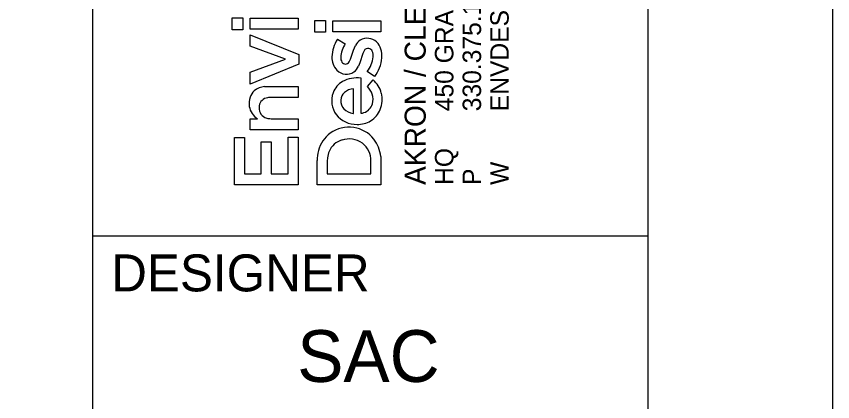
# Model space of a CAD drawing. Extents: x -1.3 to 34, y -0.5 to 22.
# Drawn here: x 31.794 to 34, y 2.552 to 3.594 of the extents above; entities that cross this region are included whole.
import ezdxf

# ---------------------------------------------------------------- set-up
doc = ezdxf.new("R2010")
doc.units = 0
for name, color, linetype in [('SH_Border', 7, 'Continuous'), ('SH_Cut_Line', 7, 'Continuous'), ('SH_Data', 7, 'Continuous')]:
    doc.layers.add(name, color=color, linetype=linetype)

msp = doc.modelspace()

# ---------------------------------------------------------------- linework, layer by layer
at = {"layer": 'SH_Border'}
for p, q in [((32, 0.5), (32, 21.5)), ((32, 3), (33.5, 3))]:
    msp.add_line(p, q, dxfattribs=at)
msp.add_lwpolyline([(1.5, 21.5), (33.5, 21.5), (33.5, 0.5), (1.5, 0.5)], close=True, dxfattribs=at)
at = {"layer": 'SH_Cut_Line'}
msp.add_lwpolyline([(0, 0), (34, 0), (34, 22), (0, 22)], close=True, dxfattribs=at)
at = {"layer": 'SH_Data'}
for p, q in [((32.3771, 3.5582), (32.3771, 3.5903)), ((32.3771, 3.5903), (32.4054, 3.5903)), ((32.4054, 3.5903), (32.4054, 3.5582)), ((32.4254, 3.5594), (32.4254, 3.5893)), ((32.4254, 3.5893), (32.5557, 3.5893)), ((32.5557, 3.5893), (32.5557, 3.5594)), ((32.6005, 3.5511), (32.6005, 3.5832)), ((32.6005, 3.5832), (32.6289, 3.5832)), ((32.6289, 3.5832), (32.6289, 3.5511)), ((32.6489, 3.5523), (32.6489, 3.5822)), ((32.6489, 3.5822), (32.7792, 3.5822)), ((32.7792, 3.5822), (32.7792, 3.5523)), ((32.4054, 3.5582), (32.3771, 3.5582)), ((32.5557, 3.5594), (32.4254, 3.5594)), ((32.7792, 3.5523), (32.6489, 3.5523)), ((32.4254, 3.5133), (32.4254, 3.5446)), ((32.4254, 3.5446), (32.5567, 3.4913)), ((32.6289, 3.5511), (32.6005, 3.5511)), ((32.6615, 3.5321), (32.6827, 3.5203)), ((32.5212, 3.478), (32.4254, 3.5133)), ((32.7048, 3.5026), (32.7104, 3.5153)), ((32.5567, 3.4913), (32.5567, 3.4644)), ((32.6967, 3.4787), (32.7048, 3.5026)), ((32.7298, 3.4933), (32.7221, 3.4688)), ((32.7334, 3.501), (32.7298, 3.4933)), ((32.4254, 3.4429), (32.5212, 3.478)), ((32.5567, 3.4644), (32.4254, 3.4109)), ((32.693, 3.4712), (32.6967, 3.4787)), ((32.7221, 3.4688), (32.7182, 3.4592)), ((32.4254, 3.4109), (32.4254, 3.4429)), ((32.7621, 3.4314), (32.742, 3.4447)), ((32.7245, 3.4275), (32.7246, 3.3319)), ((32.7423, 3.4046), (32.7577, 3.422)), ((32.4644, 3.404), (32.4729, 3.4044)), ((32.4729, 3.4044), (32.5557, 3.4044)), ((32.5557, 3.4044), (32.5557, 3.3746)), ((32.7049, 3.3318), (32.7049, 3.3983)), ((32.5557, 3.3746), (32.4814, 3.3746)), ((32.7036, 3.3317), (32.7049, 3.3318)), ((32.4254, 3.2875), (32.4254, 3.3173)), ((32.4254, 3.3173), (32.4455, 3.3173)), ((32.4822, 3.3173), (32.5557, 3.3173)), ((32.5557, 3.3173), (32.5557, 3.2876)), ((32.5557, 3.2876), (32.4254, 3.2875)), ((32.383, 3.1379), (32.383, 3.266)), ((32.383, 3.266), (32.4101, 3.266)), ((32.4101, 3.266), (32.4101, 3.1683)), ((32.5286, 3.1683), (32.5286, 3.2672)), ((32.5286, 3.2672), (32.5557, 3.2672)), ((32.5557, 3.2672), (32.5557, 3.1379)), ((32.455, 3.1683), (32.455, 3.2549)), ((32.455, 3.2549), (32.4822, 3.2549)), ((32.4822, 3.2549), (32.4822, 3.1683)), ((32.6064, 3.138), (32.6064, 3.204)), ((32.6347, 3.2118), (32.6341, 3.2023)), ((32.6341, 3.2023), (32.6341, 3.1684)), ((32.7515, 3.1683), (32.7515, 3.2024)), ((32.7785, 3.215), (32.7792, 3.2021)), ((32.7792, 3.2021), (32.7792, 3.138)), ((32.4101, 3.1683), (32.455, 3.1683)), ((32.4822, 3.1683), (32.5286, 3.1683)), ((32.6341, 3.1684), (32.7515, 3.1683)), ((32.5557, 3.1379), (32.383, 3.1379)), ((32.7792, 3.138), (32.6064, 3.138))]:
    msp.add_line(p, q, dxfattribs=at)
for points in [[(32.3771, 3.5582), (32.3771, 3.5903), (32.4054, 3.5903), (32.4054, 3.5582)], [(32.4254, 3.5594), (32.4254, 3.5893), (32.5557, 3.5893), (32.5557, 3.5594)], [(32.6005, 3.5511), (32.6005, 3.5832), (32.6289, 3.5832), (32.6289, 3.5511)], [(32.6489, 3.5523), (32.6489, 3.5822), (32.7792, 3.5822), (32.7792, 3.5523)], [(32.4254, 3.4109), (32.4254, 3.4429), (32.5212, 3.478), (32.4254, 3.5133), (32.4254, 3.5446), (32.5567, 3.4913), (32.5567, 3.4644)], [(32.383, 3.1379), (32.383, 3.266), (32.4101, 3.266), (32.4101, 3.1683), (32.455, 3.1683), (32.455, 3.2549), (32.4822, 3.2549), (32.4822, 3.1683), (32.5286, 3.1683), (32.5286, 3.2672), (32.5557, 3.2672), (32.5557, 3.1379)]]:
    msp.add_lwpolyline(points, close=True, dxfattribs=at)
for points in [[(32.6615, 3.5321), (32.6827, 3.5203)], [(32.693, 3.4712), (32.6967, 3.4787), (32.7048, 3.5026), (32.7104, 3.5153)], [(32.7334, 3.501), (32.7298, 3.4933), (32.7221, 3.4688), (32.7182, 3.4592)], [(32.7621, 3.4314), (32.742, 3.4447)], [(32.7245, 3.4275), (32.7246, 3.3319)], [(32.7423, 3.4046), (32.7577, 3.422)], [(32.4644, 3.404), (32.4729, 3.4044), (32.5557, 3.4044), (32.5557, 3.3746), (32.4814, 3.3746)], [(32.7036, 3.3317), (32.7049, 3.3318), (32.7049, 3.3983)], [(32.4254, 3.2875), (32.4254, 3.3173), (32.4455, 3.3173)], [(32.4822, 3.3173), (32.5557, 3.3173), (32.5557, 3.2876), (32.4254, 3.2875)], [(32.7785, 3.215), (32.7792, 3.2021), (32.7792, 3.138), (32.6064, 3.138)], [(32.6064, 3.138), (32.6064, 3.204)], [(32.6347, 3.2118), (32.6341, 3.2023), (32.6341, 3.1684), (32.7515, 3.1683), (32.7515, 3.2024)]]:
    msp.add_lwpolyline(points, dxfattribs=at)
for centre, radius, start, end in [((32.7364, 3.4826), 0.0897, 146.531, 178.7571), ((32.7364, 3.4826), 0.0897, 146.531, 178.7571), ((32.7406, 3.5026), 0.0326, 80.1719, 122.5197), ((32.7406, 3.5026), 0.0326, 80.1719, 122.5197), ((32.7428, 3.4982), 0.0367, 47.7934, 84.6892), ((32.7428, 3.4982), 0.0367, 47.7934, 84.6892), ((32.7452, 3.4789), 0.0749, 146.5112, 176.9101), ((32.7452, 3.4789), 0.0749, 146.5112, 176.9101), ((32.7466, 3.4971), 0.0405, 125.5118, 153.4159), ((32.7466, 3.4971), 0.0405, 125.5118, 153.4159), ((32.7379, 3.4946), 0.0427, 14.9966, 46.2063), ((32.7379, 3.4946), 0.0427, 14.9966, 46.2063), ((32.7438, 3.4963), 0.0114, 76.6609, 155.7053), ((32.7438, 3.4963), 0.0114, 76.6609, 155.7053), ((32.744, 3.4951), 0.0126, 21.5098, 78.5262), ((32.744, 3.4951), 0.0126, 21.5098, 78.5262), ((32.7259, 3.4877), 0.0321, 354.5726, 22.068), ((32.7259, 3.4877), 0.0321, 354.5726, 22.068), ((32.7104, 3.4867), 0.0712, 355.8306, 15.3914), ((32.7104, 3.4867), 0.0712, 355.8306, 15.3914), ((32.6967, 3.4824), 0.0501, 177.5366, 222.7932), ((32.6967, 3.4824), 0.0501, 177.5366, 222.7932), ((32.6931, 3.4823), 0.0228, 178.4747, 211.0868), ((32.6931, 3.4823), 0.0228, 178.4747, 211.0868), ((32.6833, 3.4767), 0.0115, 212.2368, 268.3777), ((32.6833, 3.4767), 0.0115, 212.2368, 268.3777), ((32.6834, 3.4759), 0.0107, 267.716, 333.7337), ((32.6834, 3.4759), 0.0107, 267.716, 333.7337), ((32.6825, 3.4915), 0.0757, 321.811, 354.7969), ((32.6825, 3.4915), 0.0757, 321.811, 354.7969), ((32.6895, 3.4882), 0.0922, 321.9777, 355.8738), ((32.6895, 3.4882), 0.0922, 321.9777, 355.8738), ((32.686, 3.4753), 0.0375, 225.9854, 302.4797), ((32.686, 3.4753), 0.0375, 225.9854, 302.4797), ((32.681, 3.4758), 0.0408, 308.0877, 335.9874), ((32.681, 3.4758), 0.0408, 308.0877, 335.9874), ((32.7152, 3.3441), 0.0838, 83.615, 118.2876), ((32.7152, 3.3441), 0.0838, 83.615, 118.2876), ((32.7174, 3.3717), 0.0644, 13.5336, 51.3615), ((32.7174, 3.3717), 0.0644, 13.5336, 51.3615), ((32.4687, 3.3543), 0.0499, 94.9696, 130.2225), ((32.4687, 3.3543), 0.0499, 94.9696, 130.2225), ((32.7024, 3.3691), 0.0558, 118.8308, 160.6244), ((32.7024, 3.3691), 0.0558, 118.8308, 160.6244), ((32.7079, 3.3561), 0.0424, 94.008, 130.8817), ((32.7079, 3.3561), 0.0424, 94.008, 130.8817), ((32.7038, 3.3656), 0.0549, 19.0357, 45.4406), ((32.7038, 3.3656), 0.0549, 19.0357, 45.4406), ((32.4635, 3.3626), 0.0402, 132.2219, 161.6818), ((32.4635, 3.3626), 0.0402, 132.2219, 161.6818), ((32.7104, 3.3661), 0.0644, 160.5201, 215.7831), ((32.7104, 3.3661), 0.0644, 160.5201, 215.7831), ((32.7005, 3.3663), 0.0298, 132.9851, 177.179), ((32.7005, 3.3663), 0.0298, 132.9851, 177.179), ((32.7107, 3.3697), 0.047, 344.6059, 17.007), ((32.7107, 3.3697), 0.047, 344.6059, 17.007), ((32.7064, 3.3692), 0.0758, 339.3542, 13.3785), ((32.7064, 3.3692), 0.0758, 339.3542, 13.3785), ((32.4787, 3.3582), 0.056, 162.2736, 187.7919), ((32.4787, 3.3582), 0.056, 162.2736, 187.7919), ((32.4748, 3.3487), 0.025, 103.6865, 182.2187), ((32.4748, 3.3487), 0.025, 103.6865, 182.2187), ((32.4811, 3.3286), 0.046, 89.6049, 105.3284), ((32.4811, 3.3286), 0.046, 89.6049, 105.3284), ((32.7017, 3.365), 0.0311, 175.0013, 223.283), ((32.7017, 3.365), 0.0311, 175.0013, 223.283), ((32.7224, 3.3671), 0.035, 288.0077, 343.5508), ((32.7224, 3.3671), 0.035, 288.0077, 343.5508), ((32.4703, 3.358), 0.0476, 188.962, 238.7037), ((32.4703, 3.358), 0.0476, 188.962, 238.7037), ((32.4773, 3.3456), 0.0276, 175.5854, 255.1439), ((32.4773, 3.3456), 0.0276, 175.5854, 255.1439), ((32.7089, 3.3736), 0.0423, 225.0619, 262.7974), ((32.7089, 3.3736), 0.0423, 225.0619, 262.7974), ((32.7247, 3.3522), 0.0202, 269.7003, 294.8711), ((32.7247, 3.3522), 0.0202, 269.7003, 294.8711), ((32.7189, 3.3652), 0.0626, 300.9427, 338.7323), ((32.7189, 3.3652), 0.0626, 300.9427, 338.7323), ((32.4818, 3.3595), 0.0422, 254.0916, 270.5284), ((32.4818, 3.3595), 0.0422, 254.0916, 270.5284), ((32.7125, 3.3705), 0.0687, 217.7452, 271.6543), ((32.7125, 3.3705), 0.0687, 217.7452, 271.6543), ((32.7155, 3.3724), 0.0706, 269.2048, 300.3341), ((32.7155, 3.3724), 0.0706, 269.2048, 300.3341), ((32.6923, 3.2079), 0.0864, 81.194, 125.9984), ((32.6923, 3.2079), 0.0864, 81.194, 125.9984), ((32.6946, 3.2113), 0.0827, 37.8521, 82.402), ((32.6946, 3.2113), 0.0827, 37.8521, 82.402), ((32.6939, 3.2089), 0.0865, 127.2362, 165.148), ((32.6939, 3.2089), 0.0865, 127.2362, 165.148), ((32.6889, 3.2078), 0.054, 106.1881, 157.3861), ((32.6889, 3.2078), 0.054, 106.1881, 157.3861), ((32.6928, 3.1986), 0.0639, 55.6727, 107.2093), ((32.6928, 3.1986), 0.0639, 55.6727, 107.2093), ((32.6929, 3.205), 0.0587, 357.4662, 52.2665), ((32.6929, 3.205), 0.0587, 357.4662, 52.2665), ((32.6859, 3.2057), 0.0931, 5.7333, 37.304), ((32.6859, 3.2057), 0.0931, 5.7333, 37.304), ((32.7143, 3.2028), 0.1078, 164.7861, 179.3704), ((32.7143, 3.2028), 0.1078, 164.7861, 179.3704), ((32.6983, 3.2039), 0.0641, 157.3571, 172.9275), ((32.6983, 3.2039), 0.0641, 157.3571, 172.9275)]:
    msp.add_arc(centre, radius, start, end, dxfattribs=at)

# ---------------------------------------------------------------- texts
for s, height, p in [('450 GRANT ST., AKRON, OH  44311', 0.049846, (32.9749, 3.3374)), ('AKRON / CLEVELAND / COLUMBUS', 0.056969, (32.9001, 3.138)), ('ENVDESIGNGROUP.COM', 0.049846, (33.1244, 3.3374)), ('330.375.1390', 0.049846, (33.0497, 3.3374)), ('HQ ', 0.04985, (32.9749, 3.138)), ('W', 0.0498, (33.1244, 3.138)), ('P', 0.0498, (33.0497, 3.138))]:
    msp.add_text(s, height=height, rotation=90, dxfattribs=at).set_placement(p)
for s, height, p in [('DESIGNER', 0.1, (32.05, 2.85)), ('SAC', 0.14, (32.5528, 2.605))]:
    msp.add_text(s, height=height, dxfattribs=at).set_placement(p)

doc.saveas('drawing.dxf')
